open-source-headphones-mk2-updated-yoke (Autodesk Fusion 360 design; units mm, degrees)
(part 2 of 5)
sketch "Shell Hexagon Pattern" plane through (0, 0, 98) normal (0, 0, 1) x axis (-1, 0, 0)
  line L1 (19.1469, -26.6365) -> (22.8469, -28.7727)
  line L2 (19.1469, -22.3642) -> (19.1469, -26.6365)
  line L3 (22.8469, -20.228) -> (19.1469, -22.3642)
  line L4 (26.5469, -22.3642) -> (22.8469, -20.228)
  line L5 (26.5469, -26.6365) -> (26.5469, -22.3642)
  line L6 (22.8469, -28.7727) -> (26.5469, -26.6365)
  line L7 (-26.5469, 22.3642) -> (-22.8469, 20.228)
  line L8 (-26.5469, 26.6365) -> (-26.5469, 22.3642)
  line L9 (-22.8469, 28.7727) -> (-26.5469, 26.6365)
  line L10 (-19.1469, 26.6365) -> (-22.8469, 28.7727)
  line L11 (-19.1469, 22.3642) -> (-19.1469, 26.6365)
  line L12 (-22.8469, 20.228) -> (-19.1469, 22.3642)
  line L13 (19.1469, 22.3642) -> (22.8469, 20.228)
  line L14 (19.1469, 26.6365) -> (19.1469, 22.3642)
  line L15 (22.8469, 28.7727) -> (19.1469, 26.6365)
  line L16 (26.5469, 26.6365) -> (22.8469, 28.7727)
  line L17 (26.5469, 22.3642) -> (26.5469, 26.6365)
  line L18 (22.8469, 20.228) -> (26.5469, 22.3642)
  line L19 (-26.5469, -26.6365) -> (-22.8469, -28.7727)
  line L20 (-26.5469, -22.3642) -> (-26.5469, -26.6365)
  line L21 (-22.8469, -20.228) -> (-26.5469, -22.3642)
  line L22 (-19.1469, -22.3642) -> (-22.8469, -20.228)
  line L23 (-19.1469, -26.6365) -> (-19.1469, -22.3642)
  line L24 (-22.8469, -28.7727) -> (-19.1469, -26.6365)
  curve K1 (-7.3164, 50.178) -> (-7.3164, 50.178)
  line L25 (0, 51) -> (0, 0)
  line L26 (1, 24.5003) -> (0, 24.5003)
  line L27 (4.6, 24.5003) -> (1, 24.5003)
  line L28 (4.6, 20.3434) -> (1, 22.4219)
  line L29 (8.2, 22.4219) -> (4.6, 20.3434)
  line L30 (8.2, 26.5788) -> (8.2, 22.4219)
  line L31 (4.6, 28.6573) -> (8.2, 26.5788)
  line L32 (1, 26.5788) -> (4.6, 28.6573)
  line L33 (1, 22.4219) -> (1, 26.5788)
  line L34 (10.2, 24.5003) -> (8.2, 24.5003)
  line L35 (10.2, 26.5788) -> (13.8, 28.6573)
  line L36 (10.2, 22.4219) -> (10.2, 26.5788)
  line L37 (13.8, 20.3434) -> (10.2, 22.4219)
  line L38 (17.4, 22.4219) -> (13.8, 20.3434)
  line L39 (17.4, 26.5788) -> (17.4, 22.4219)
  line L40 (13.8, 28.6573) -> (17.4, 26.5788)
  line L41 (-1, 26.5788) -> (-1, 22.4219)
  line L42 (-4.6, 28.6573) -> (-1, 26.5788)
  line L43 (-8.2, 26.5788) -> (-4.6, 28.6573)
  line L44 (-8.2, 22.4219) -> (-8.2, 26.5788)
  line L45 (-4.6, 20.3434) -> (-8.2, 22.4219)
  line L46 (-1, 22.4219) -> (-4.6, 20.3434)
  line L47 (-13.8, 28.6573) -> (-10.2, 26.5788)
  line L48 (-17.4, 26.5788) -> (-13.8, 28.6573)
  line L49 (-17.4, 22.4219) -> (-17.4, 26.5788)
  line L50 (-13.8, 20.3434) -> (-17.4, 22.4219)
  line L51 (-10.2, 26.5788) -> (-10.2, 22.4219)
  line L52 (-10.2, 22.4219) -> (-13.8, 20.3434)
  line L53 (-1, 24.5003) -> (0, 24.5003)
  line L54 (16.6, 29.3501) -> (15.6, 27.618)
  line L55 (18.4, 28.3109) -> (14.8, 30.3893)
  line L56 (22, 30.3893) -> (18.4, 28.3109)
  line L57 (22, 34.5462) -> (22, 30.3893)
  line L58 (18.4, 36.6247) -> (22, 34.5462)
  line L59 (14.8, 34.5462) -> (18.4, 36.6247)
  line L60 (14.8, 30.3893) -> (14.8, 34.5462)
  line L61 (5.6, 30.3893) -> (5.6, 34.5462)
  line L62 (9.2, 28.3109) -> (5.6, 30.3893)
  line L63 (12.8, 30.3893) -> (9.2, 28.3109)
  line L64 (12.8, 34.5462) -> (12.8, 30.3893)
  line L65 (5.6, 34.5462) -> (9.2, 36.6247)
  line L66 (9.2, 36.6247) -> (12.8, 34.5462)
  line L67 (-3.6, 30.3893) -> (-3.6, 34.5462)
  line L68 (0, 28.3109) -> (-3.6, 30.3893)
  line L69 (3.6, 30.3893) -> (0, 28.3109)
  line L70 (3.6, 34.5462) -> (3.6, 30.3893)
  line L71 (-3.6, 34.5462) -> (0, 36.6247)
  line L72 (0, 36.6247) -> (3.6, 34.5462)
  line L73 (-12.8, 30.3893) -> (-12.8, 34.5462)
  line L74 (-9.2, 28.3109) -> (-12.8, 30.3893)
  line L75 (-5.6, 30.3893) -> (-9.2, 28.3109)
  line L76 (-5.6, 34.5462) -> (-5.6, 30.3893)
  line L77 (-12.8, 34.5462) -> (-9.2, 36.6247)
  line L78 (-9.2, 36.6247) -> (-5.6, 34.5462)
  line L79 (-14.8, 32.4678) -> (-12.8, 32.4678)
  line L80 (-27.6, 28.3109) -> (-31.2, 30.3893)
  line L81 (-24, 30.3893) -> (-27.6, 28.3109)
  line L82 (-24, 34.5462) -> (-24, 30.3893)
  line L83 (-27.6, 36.6247) -> (-24, 34.5462)
  line L84 (-31.2, 30.3893) -> (-31.2, 34.5462)
  line L85 (-31.2, 34.5462) -> (-27.6, 36.6247)
  line L86 (-18.4, 28.3109) -> (-22, 30.3893)
  line L87 (-14.8, 30.3893) -> (-18.4, 28.3109)
  line L88 (-14.8, 34.5462) -> (-14.8, 30.3893)
  line L89 (-18.4, 36.6247) -> (-14.8, 34.5462)
  line L90 (-22, 30.3893) -> (-22, 34.5462)
  line L91 (-22, 34.5462) -> (-18.4, 36.6247)
  line L92 (24, 32.4678) -> (22, 32.4678)
  line L93 (24, 34.5462) -> (27.6, 36.6247)
  line L94 (24, 30.3893) -> (24, 34.5462)
  line L95 (27.6, 28.3109) -> (24, 30.3893)
  line L96 (31.2, 30.3893) -> (27.6, 28.3109)
  line L97 (31.2, 34.5462) -> (31.2, 30.3893)
  line L98 (27.6, 36.6247) -> (31.2, 34.5462)
  line L99 (30.4, 27.618) -> (29.4, 29.3501)
  line L100 (32.2, 28.6573) -> (35.8, 26.5788)
  line L101 (28.6, 26.5788) -> (32.2, 28.6573)
  line L102 (28.6, 22.4219) -> (28.6, 26.5788)
  line L103 (32.2, 20.3434) -> (28.6, 22.4219)
  line L104 (35.8, 22.4219) -> (32.2, 20.3434)
  line L105 (35.8, 26.5788) -> (35.8, 22.4219)
  line L106 (15.6, 37.3175) -> (16.6, 35.5855)
  line L107 (23, 36.2783) -> (19.4, 38.3568)
  line L108 (26.6, 38.3568) -> (23, 36.2783)
  line L109 (26.6, 42.5137) -> (26.6, 38.3568)
  line L110 (23, 44.5921) -> (26.6, 42.5137)
  line L111 (19.4, 42.5137) -> (23, 44.5921)
  line L112 (19.4, 38.3568) -> (19.4, 42.5137)
  line L113 (10.2, 38.3568) -> (10.2, 42.5137)
  line L114 (13.8, 36.2783) -> (10.2, 38.3568)
  line L115 (17.4, 38.3568) -> (13.8, 36.2783)
  line L116 (17.4, 42.5137) -> (17.4, 38.3568)
  line L117 (10.2, 42.5137) -> (13.8, 44.5921)
  line L118 (13.8, 44.5921) -> (17.4, 42.5137)
  line L119 (1, 38.3568) -> (1, 42.5137)
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  point P1 (0, 0)
  point P28 (0, 0)
  point P29 (0, 51)
  point P30 (0, 24.5003)
  point P32 (4.6, 24.5003)
  point P39 (4.6, 24.5003)
  point P40 (8.2, 24.5003)
  point P62 (15.6, 27.618)
  point P88 (-12.8, 32.4678)
  point P102 (22, 32.4678)
  point P110 (29.4, 29.3501)
  point P118 (16.6, 35.5855)
  point P188 (15.6, 21.3827)
  point P232 (-29.4, 29.3501)
  point P557 (0, 0)
  point P593 (0, 0)
  point P425 (-4.6, -24.5003)
  point P534 (-4.6, -24.5003)
  point P31 (1, 24.5003)
  point P41 (10.2, 24.5003)
  point P54 (-1, 24.5003)
  point P61 (0, 24.5003)
  point P63 (16.6, 29.3501)
  point P89 (-14.8, 32.4678)
  point P103 (24, 32.4678)
  point P111 (30.4, 27.618)
  point P119 (15.6, 37.3175)
  point P156 (6.4, 43.5529)
  point P157 (7.4, 45.285)
  point P189 (16.6, 19.6506)
  point P233 (-30.4, 27.618)
  point P252 (29.4, 13.4152)
  point P253 (30.4, 11.6832)
  point P308 (-35.8, 8.5655)
  point P309 (-37.8, 8.5655)
  point P316 (30.4, 5.4478)
  point P317 (29.4, 3.7157)
  point P441 (-1, -24.5003)
  point P716 (0, -24.5003)
  point P423 (-10.2, -24.5003)
  point P424 (-8.2, -24.5003)
  point P571 (0, -24.5003)
  point P701 (1, -24.5003)
  point P535 (-15.6, -27.618)
  point P537 (-16.6, -29.3501)
  point P717 (12.8, -32.4678)
  point P729 (14.8, -32.4678)
  point P547 (-22, -32.4678)
  point P548 (-24, -32.4678)
  point P549 (-29.4, -29.3501)
  point P550 (-30.4, -27.618)
  point P541 (-16.6, -35.5855)
  point P558 (-15.6, -37.3175)
  point P536 (-7.4, -45.285)
  point P559 (-6.4, -43.5529)
  point P712 (-16.6, -19.6506)
  point P714 (-15.6, -21.3827)
  point P484 (30.4, -27.618)
  point P488 (29.4, -29.3501)
  point P560 (-29.4, -13.4152)
  point P561 (-30.4, -11.6832)
  point P563 (35.8, -8.5655)
  point P564 (37.8, -8.5655)
  point P562 (-30.4, -5.4478)
  point P565 (-29.4, -3.7157)
  coincident P1 P28
  coincident K1 P29
  vertical L25
  coincident L25 P30
  perpendicular L25 L26
  parallel L26 L27
  coincident P32 P39
  midpoint L30 P40
  perpendicular L30 L34
  midpoint L40 P62
  perpendicular L40 L54
  midpoint L73 P88
  perpendicular L73 L79
  midpoint L57 P102
  perpendicular L57 L92
  midpoint L96 P110
  perpendicular L96 L99
  midpoint L59 P118
  perpendicular L59 L106
  midpoint L38 P188
  midpoint L80 P232
  coincident P557 P593
  coincident P425 P534
  dimension "d175" distance P30 P31 = 1
  dimension "d180" distance P31 P32 = 3.6
  dimension "d181" distance P39 L33 = 3.6
  dimension "d182" distance P40 P41 = 2
  dimension "d183" distance P54 P61 = 1
  dimension "d184" distance P62 P63 = 2
  dimension "d185" distance P88 P89 = 2
  dimension "d186" distance P102 P103 = 2
  dimension "d187" distance P110 P111 = 2
  dimension "d188" distance P118 P119 = 2
  dimension "d189" distance P156 P157 = 2
  dimension "d190" distance P188 P189 = 2
  dimension "d191" distance P232 P233 = 2
  dimension "d192" distance P252 P253 = 2
  dimension "d193" distance P308 P309 = 2
  dimension "d194" distance P316 P317 = 2
  dimension "d195" distance P441 P716 = 1
  dimension "d196" distance P425 P441 = 3.6
  dimension "d197" distance = 3.6
  dimension "d198" distance P423 P424 = 2
  dimension "d199" distance P571 P701 = 1
  dimension "d200" distance P535 P537 = 2
  dimension "d201" distance P717 P729 = 2
  dimension "d202" distance P547 P548 = 2
  dimension "d203" distance P549 P550 = 2
  dimension "d204" distance P541 P558 = 2
  dimension "d205" distance P536 P559 = 2
  dimension "d206" distance P712 P714 = 2
  dimension "d207" distance P484 P488 = 2
  dimension "d208" distance P560 P561 = 2
  dimension "d209" distance P563 P564 = 2
  dimension "d210" distance P562 P565 = 2
sketch "Sketch12" plane through (0, 0, 98) normal (0, 0, 1) x axis (-1, 0, 0)
  line L1 (19.1469, -26.6365) -> (22.8469, -28.7727)
  line L2 (19.1469, -22.3642) -> (19.1469, -26.6365)
  line L3 (22.8469, -20.228) -> (19.1469, -22.3642)
  line L4 (26.5469, -22.3642) -> (22.8469, -20.228)
  line L5 (26.5469, -26.6365) -> (26.5469, -22.3642)
  line L6 (22.8469, -28.7727) -> (26.5469, -26.6365)
  line L7 (-26.5469, 22.3642) -> (-22.8469, 20.228)
  line L8 (-26.5469, 26.6365) -> (-26.5469, 22.3642)
  line L9 (-22.8469, 28.7727) -> (-26.5469, 26.6365)
  line L10 (-19.1469, 26.6365) -> (-22.8469, 28.7727)
  line L11 (-19.1469, 22.3642) -> (-19.1469, 26.6365)
  line L12 (-22.8469, 20.228) -> (-19.1469, 22.3642)
  line L13 (19.1469, 22.3642) -> (22.8469, 20.228)
  line L14 (19.1469, 26.6365) -> (19.1469, 22.3642)
  line L15 (22.8469, 28.7727) -> (19.1469, 26.6365)
  line L16 (26.5469, 26.6365) -> (22.8469, 28.7727)
  line L17 (26.5469, 22.3642) -> (26.5469, 26.6365)
  line L18 (22.8469, 20.228) -> (26.5469, 22.3642)
  line L19 (-26.5469, -26.6365) -> (-22.8469, -28.7727)
  line L20 (-26.5469, -22.3642) -> (-26.5469, -26.6365)
  line L21 (-22.8469, -20.228) -> (-26.5469, -22.3642)
  line L22 (-19.1469, -22.3642) -> (-22.8469, -20.228)
  line L23 (-19.1469, -26.6365) -> (-19.1469, -22.3642)
  line L24 (-22.8469, -28.7727) -> (-19.1469, -26.6365)
  curve K1 (-7.3164, 50.178) -> (-7.3164, 50.178)
  curve K2 (0, -48.6) -> (0, 48.6)
  curve K3 (38.6, 0) -> (-38.6, 0)
  closed curve K4 centre (0, 0)
  point P29 (0, 48.6)
  point P30 (0, -48.6)
  point P31 (-38.6, 0)
  point P32 (38.6, 0)
  coincident K4 P29
  coincident K4 P30
  coincident K4 P31
  coincident K4 P32
  dimension "d217" distance K4 = 97.2
  dimension "d218" = 77.2
extrude "Extrude25" cut sketch "Sketch12" profile of L1 L2 L3 L4 L5 L6 L7 L8 L9 L10 L11 L12 L13 L14 L15 L16 L17 L18 L19 L20 L21 L22 L23 L24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 against normal blind 4 bodies "Closed Shell (1) (1)", "Closed Shell (1) (2)", "Closed Shell (1) (3)", "Open Shell"
extrude "Extrude26" add sketch "Shell Hexagon Pattern" against normal blind 4 bodies "Closed Shell (1)", "Closed Shell (1) (1)", "Closed Shell (1) (2)", "Closed Shell (1) (3)"
chamfer "Chamfer8" distance 0.24 distance 1
sketch "Headband Arc" plane through (0, 0, 0) normal (0, 0, 1) x axis (1, 0, 0)
  line L1 (0, -165) -> (0, -75)
  line L2 (85, -165) -> (0, -165)
  line L3 (0, -71.5) -> (0, -75)
  line L4 (88.5, -165) -> (85, -165)
  line L5 (91.4952, -168.75) -> (85, -165)
  line L6 (92.5, -165) -> (85, -165)
  line L7 (81.4952, -186.0705) -> (91.4952, -168.75)
  line L8 (69.8038, -179.3205) -> (81.4952, -186.0705)
  line L9 (73.3038, -173.2583) -> (69.8038, -179.3205)
  line L10 (77.7713, -183.9205) -> (87.7713, -166.6)
  line L11 (81.2713, -177.8583) -> (73.3038, -173.2583)
  line L12 (87.2289, -149.2103) -> (91.4952, -168.75)
  closed curve K1 centre (0, -165)
  closed curve K2 centre (0, -165)
  point P4 (85, -165)
  point P7 (88.5, -165)
  point P16 (81.2713, -177.8583)
  point P17 (87.2289, -149.2103)
  point P18 (84.7553, -171.8238)
  point P19 (88.4796, -167.0089)
  point P2 (0, -75)
  point P3 (0, -165)
  point P6 (0, -71.5)
  point P9 (91.4952, -168.75)
  point P11 (81.4952, -186.0705)
  point P12 (69.8038, -179.3205)
  point P13 (73.3038, -173.2583)
  vertical L1
  perpendicular L1 L2
  coincident P4 K1
  parallel L1 L3
  parallel L2 L4
  coincident P7 K2
  horizontal L6
  perpendicular L5 L7
  perpendicular L7 L8
  perpendicular L8 L9
  coincident L10 P16
  perpendicular L10 L11
  coincident P17 K2
  coincident L10 P18
  coincident L5 P19
  dimension "d225" distance P2 P3 = 90
  dimension "d226" distance P3 P4 = 85
  dimension "d227" distance P2 P6 = 3.5
  dimension "d228" distance P4 P7 = 3.5
  dimension "d229" angle L5 L6 = 30
  dimension "d230" distance P4 P9 = 7.5
  dimension "d231" distance P9 P11 = 20
  dimension "d232" distance P11 P12 = 13.5
  dimension "d233" distance P12 P13 = 7
  dimension "d234" = 4.3
  dimension "d235" distance P9 P17 = 20
extrude "Extrude1" new body sketch "Headband Arc" profile of K1 L3 L4 K2 L5 L7 L8 L9 L10 L11 L12 along normal blind 36
sketch "Yoke Hole" plane through (-60.1971, -104.2644, 0) normal (-0.5, -0.866, 0) x axis (0.866, -0.5, 0)
  line L1 (163.6122, 0) -> (150.1122, 0)
  line L2 (163.6122, 36) -> (163.6122, 0)
  line L3 (150.1122, 36) -> (163.6122, 36)
  line L4 (150.1122, 0) -> (150.1122, 36)
  line L5 (152.6122, 18) -> (150.1122, 18)
  line L6 (155.7122, 18) -> (152.6122, 18)
  line L7 (152.6122, 14.9) -> (158.8122, 14.9)
  line L8 (152.6122, 21.1) -> (152.6122, 14.9)
  line L9 (158.8122, 21.1) -> (152.6122, 21.1)
  line L10 (158.8122, 14.9) -> (158.8122, 21.1)
  line L11 (152.6122, 21.1) -> (158.8122, 14.9)
  line L12 (158.8122, 21.1) -> (152.6122, 14.9)
  circle C1 centre (155.7122, 18) radius 3.1
  circle C2 centre (155.7122, 18) radius 2.1
  point P6 (150.1122, 18)
  point P13 (155.7122, 18)
  point P8 (155.7122, 18)
  point P14 (155.7122, 18)
  point P7 (152.6122, 18)
  point P15 (155.7122, 18)
  point P11 (152.6122, 21.1)
  point P12 (158.8122, 21.1)
  point P10 (152.6122, 14.9)
  midpoint L4 P6
  perpendicular L4 L5
  parallel L5 L6
  horizontal L7
  perpendicular L7 L8
  parallel L7 L9
  parallel L8 L10
  coincident L11 P13
  coincident L12 P13
  coincident P8 P13
  coincident P13 P14
  coincident P7 C1
  coincident P13 P15
  dimension "d240" distance P6 P7 = 2.5
  dimension "d241" distance P7 P8 = 3.1
  dimension "d242" distance P11 P12 = 6.2
  dimension "d243" distance P10 P11 = 6.2
  dimension "d244" diameter C2 = 4.2
extrude "Extrude2" cut sketch "Yoke Hole" profile of C2 against normal blind 7
extrude "Extrude3" cut sketch "Yoke Hole" profile of L7 L8 L9 C1 C2 against normal blind 5
sketch "Sketch2" plane through (141.6923, -81.8061, 0) normal (0.866, -0.5, 0) x axis (0.5, 0.866, 0)
  line L1 (-100.3942, 0) -> (-120.3942, 0)
  line L2 (-100.3942, 36) -> (-100.3942, 0)
  line L3 (-120.3942, 36) -> (-100.3942, 36)
  line L4 (-120.3942, 0) -> (-120.3942, 36)
  line L5 (-120.3942, 35) -> (-100.3942, 1)
  line L6 (-105.6231, 35.681) -> (-117.6911, 23.613)
  line L7 (-100.3942, 1) -> (-100.3942, 35)
  line L8 (-103.0973, 12.387) -> (-114.3233, 23.613)
  line L9 (-103.9392, 33.9971) -> (-114.3233, 23.613)
  line L10 (-113.2007, 12.387) -> (-120.217, 19.4033)
  line L11 (-100.3942, 35) -> (-120.3942, 35)
  line L12 (-106.4651, 12.387) -> (-117.6911, 23.613)
  line L13 (-120.3942, 36) -> (-100.3942, 36)
  line L14 (-120.217, 5.3707) -> (-113.2007, 12.387)
  line L15 (-100.5714, 30.6293) -> (-107.5877, 23.613)
  line L16 (-115.1653, 0.319) -> (-103.0973, 12.387)
  line L17 (-118.5331, 21.0872) -> (-118.5331, 3.6868)
  line L18 (-118.5331, 3.6868) -> (-107.307, 14.9128)
  line L19 (-100.3942, 0) -> (-120.3942, 0)
  line L20 (-107.307, 33.9971) -> (-103.9392, 33.9971)
  line L21 (-120.3942, 1) -> (-100.3942, 1)
  line L22 (-113.4813, 2.0029) -> (-116.8492, 2.0029)
  line L23 (-116.8492, 2.0029) -> (-106.4651, 12.387)
  line L24 (-102.2553, 32.3132) -> (-102.2553, 14.9128)
  line L25 (-102.2553, 14.9128) -> (-110.9555, 23.613)
  line L26 (-108.7103, 18) -> (-112.0781, 18)
  line L27 (-107.307, 9.8611) -> (-118.5331, 21.0872)
  line L28 (-120.3942, 35) -> (-120.3942, 1)
  line L29 (-100.5714, 16.5967) -> (-107.5877, 23.613)
  line L30 (-100.3942, 35) -> (-120.3942, 1)
  line L31 (-102.2553, 32.3132) -> (-110.9555, 23.613)
  line L32 (-100.3942, 36) -> (-100.3942, 0)
  line L33 (-120.3942, 0) -> (-120.3942, 36)
  point P11 (-113.4813, 2.0029)
  point P23 (-107.307, 33.9971)
  point P38 (-112.0781, 18)
  point P37 (-108.7103, 18)
  point P36 (-110.3942, 18)
  point P33 (-120.3942, 35)
  point P35 (-100.3942, 35)
  point P39 (-120.3942, 1)
  coincident P11 L16
  coincident P23 L6
  parallel L20 L22
  midpoint P38 L12
  midpoint P37 L8
  horizontal L21
  perpendicular L21 L28
  parallel L11 L21
  parallel L7 L28
  coincident P36 L5
  coincident P36 L30
  midpoint P36 L26
  dimension "d249" distance P33 P35 = 20
  dimension "d250" distance P33 P39 = 34
sketch "Left" plane through (52.1639, 11.3894, 0) normal (0.977, 0.2133, 0) x axis (-0.2133, 0.977, 0)
  dimension "d253" = 15
sketch "Sketch4" plane through (0, 0, 36) normal (0, 0, 1) x axis (-1, 0, 0)
  line L1 (-91.4952, 168.75) -> (-81.4952, 186.0705)
  line L2 (-87.2289, 149.2103) -> (-91.4952, 168.75)
  line L3 (0, 75) -> (0, 71.5)
  line L4 (-81.2713, 177.8583) -> (-84.7553, 171.8238)
  line L5 (-73.3038, 173.2583) -> (-81.2713, 177.8583)
  line L6 (-69.8038, 179.3205) -> (-73.3038, 173.2583)
  line L7 (-81.4952, 186.0705) -> (-69.8038, 179.3205)
  line L8 (-86.3713, 169.0249) -> (-81.2713, 177.8583)
  line L9 (-84.7531, 158.1446) -> (-86.3713, 169.0249)
  closed curve K1 centre (0, 165)
  closed curve K2 centre (0, 165)
  point P9 (-81.2713, 177.8583)
  point P12 (-81.2713, 177.8583)
  point P14 (-84.7531, 158.1446)
  point P13 (-86.3713, 169.0249)
  coincident P9 P12
  perpendicular L5 L8
  coincident K2 P14
  dimension "d258" distance P12 P13 = 10.2
  dimension "d259" distance P13 P14 = 11
chamfer "Chamfer1" distance 1 distance 1
extrude "Extrude6" cut sketch "Sketch4" profile of K2 L8 L9 against normal blind 36
sketch "Sketch12" plane through (-56.6971, -98.2023, 0) normal (0.5, 0.866, 0) x axis (-0.866, 0.5, 0)
  line L1 (-150.1122, 1) -> (-151.1122, 0)
  line L2 (-150.1122, 35) -> (-150.1122, 1)
  line L3 (-151.1122, 36) -> (-150.1122, 35)
  line L4 (-159.3122, 36) -> (-151.1122, 36)
  line L5 (-159.3122, 0) -> (-159.3122, 36)
  line L6 (-151.1122, 0) -> (-159.3122, 0)
  line L7 (-151.5552, 18) -> (-153.6337, 14.4)
  line L8 (-153.6337, 21.6) -> (-151.5552, 18)
  line L9 (-157.7906, 21.6) -> (-153.6337, 21.6)
  line L10 (-159.8691, 18) -> (-157.7906, 21.6)
  line L11 (-157.7906, 14.4) -> (-159.8691, 18)
  line L12 (-153.6337, 14.4) -> (-157.7906, 14.4)
  circle C1 centre (-155.7122, 18) radius 2.1
  point P8 (-155.7122, 18)
  point P15 (-155.7122, 18)
  coincident P8 P15
  dimension "d341" distance P15 L12 = 3.6
extrude "Extrude19" cut sketch "Sketch12" profile of L5 L10 L11 along normal blind 6
extrude "Extrude20" add sketch "Sketch12" profile of L5 L10 L11 along normal blind 2
mirror "Mirror1" mirrorStitchTolerance 0.1
sketch "Sketch5" plane through (-141.6923, -81.8061, 0) normal (-0.866, -0.5, 0) x axis (0.5, -0.866, 0)
  line L1 (120.3942, 1) -> (100.3942, 1)
  line L2 (120.3942, 35) -> (120.3942, 1)
  line L3 (100.3942, 35) -> (120.3942, 35)
  line L4 (100.3942, 1) -> (100.3942, 35)
  line L5 (108.7103, 18) -> (112.0781, 18)
  line L6 (120.3942, 35) -> (100.3942, 35)
  line L7 (100.3942, 1) -> (120.3942, 1)
  line L8 (120.3942, 0) -> (100.3942, 0)
  line L9 (103.9392, 2.0029) -> (114.3233, 12.387)
  line L10 (100.3942, 36) -> (120.3942, 36)
  line L11 (100.3942, 0) -> (100.3942, 36)
  line L12 (118.5331, 14.9128) -> (118.5331, 32.3132)
  line L13 (102.2553, 3.6868) -> (110.9555, 12.387)
  line L14 (120.3942, 36) -> (120.3942, 0)
  line L15 (120.217, 30.6293) -> (113.2007, 23.613)
  line L16 (100.3942, 0) -> (100.3942, 36)
  line L17 (100.5714, 19.4033) -> (107.5877, 12.387)
  line L18 (103.0973, 23.613) -> (114.3233, 12.387)
  line L19 (100.3942, 36) -> (120.3942, 36)
  line L20 (118.5331, 32.3132) -> (107.307, 21.0872)
  line L21 (106.4651, 23.613) -> (117.6911, 12.387)
  line L22 (102.2553, 3.6868) -> (102.2553, 21.0872)
  line L23 (120.3942, 1) -> (120.3942, 35)
  line L24 (100.3942, 1) -> (120.3942, 35)
  line L25 (107.307, 26.1389) -> (118.5331, 14.9128)
  line L26 (120.3942, 0) -> (100.3942, 0)
  line L27 (105.6231, 0.319) -> (117.6911, 12.387)
  line L28 (100.3942, 35) -> (100.3942, 1)
  line L29 (113.4813, 33.9971) -> (116.8492, 33.9971)
  line L30 (113.2007, 23.613) -> (120.217, 16.5967)
  line L31 (120.3942, 36) -> (120.3942, 0)
  line L32 (100.5714, 5.3707) -> (107.5877, 12.387)
  line L33 (115.1653, 35.681) -> (103.0973, 23.613)
  line L34 (102.2553, 21.0872) -> (110.9555, 12.387)
  line L35 (116.8492, 33.9971) -> (106.4651, 23.613)
  line L36 (120.3942, 1) -> (100.3942, 35)
  line L37 (107.307, 2.0029) -> (103.9392, 2.0029)
  point P26 (113.4813, 33.9971)
  point P27 (107.307, 2.0029)
  point P28 (112.0781, 18)
  point P36 (108.7103, 18)
  point P35 (110.3942, 18)
  point P29 (120.3942, 1)
  point P31 (100.3942, 1)
  point P43 (120.3942, 35)
  coincident P26 L33
  coincident P27 L27
  parallel L29 L37
  midpoint P28 L21
  midpoint P36 L18
  perpendicular L6 L23
  parallel L6 L7
  parallel L23 L28
  coincident P35 L36
  coincident P35 L24
  midpoint P35 L5
  dimension "d264" distance P29 P31 = 20
  dimension "d265" distance P29 P43 = 34
sketch "Right" plane through (-52.1639, 11.3894, 0) normal (-0.977, 0.2133, 0) x axis (-0.2133, -0.977, 0)
  line L1 (184.3831, 1) -> (164.3831, 1)
  line L2 (184.3831, 35) -> (184.3831, 1)
  line L3 (164.3831, 35) -> (184.3831, 35)
  line L4 (164.3831, 1) -> (164.3831, 35)
  line L5 (184.3831, 36) -> (184.3831, 0)
  line L6 (164.3831, 36) -> (184.3831, 36)
  curve K1
  curve K2
  curve K3
  curve K4
  line L7 (164.3831, 0) -> (164.3831, 36)
  line L8 (184.3831, 0) -> (164.3831, 0)
  dimension "d266" Text1-Height = 15
extrude "Extrude7" cut sketch "Left" against normal blind 0.5
extrude "Extrude8" cut sketch "Sketch2" profile of L6 L8 L9 L10 L12 L14 L15 L16 L17 L18 L20 L22 L23 L24 L25 L27 L29 L31 against normal blind 0.5
extrude "Extrude9" cut sketch "Right" against normal blind 0.5
extrude "Extrude10" cut sketch "Sketch5" profile of L9 L12 L13 L15 L17 L18 L20 L21 L22 L25 L27 L29 L30 L32 L33 L34 L35 L37 against normal blind 0.5
sketch "Yoke" plane through (0, 0, 0) normal (0, 0, 1) x axis (1, 0, 0)
  line L1 (50, -150) -> (45, -150)
  line L2 (0, -90) -> (0, -95)
  line L3 (50, -150) -> (45, -150)
  line L4 (50, -155) -> (50, -150)
  line L5 (45, -155) -> (50, -155)
  line L6 (45, -150) -> (45, -155)
  line L7 (39, -155) -> (50, -155)
  line L8 (39, -161) -> (39, -155)
  line L9 (50, -161) -> (39, -161)
  line L10 (50, -155) -> (50, -161)
  line L11 (18, -90) -> (0, -90)
  line L12 (18, -97) -> (18, -90)
  line L13 (0, -97) -> (18, -97)
  line L14 (0, -90) -> (0, -97)
  line L15 (30, -102) -> (18, -90)
  line L16 (34.9706, -90) -> (18, -90)
  line L17 (50, -155) -> (45, -155)
  line L18 (50, -158) -> (50, -155)
  line L19 (45, -158) -> (50, -158)
  line L20 (45, -155) -> (45, -158)
  closed curve K1 centre (0, -150)
  closed curve K2 centre (0, -150)
  point P17 (30, -102)
  point P20 (50, -158)
  point P4 (45, -150)
  point P8 (50, -150)
  point P10 (45, -155)
  point P9 (50, -155)
  point P11 (39, -155)
  point P13 (50, -161)
  point P6 (0, -90)
  point P14 (18, -90)
  point P16 (0, -97)
  concentric K1 K2
  horizontal L3
  vertical L4
  horizontal L5
  vertical L6
  horizontal L7
  vertical L8
  horizontal L9
  vertical L10
  horizontal L11
  vertical L12
  horizontal L13
  vertical L14
  horizontal L16
  coincident K1 P17
  horizontal L17
  vertical L18
  horizontal L19
  vertical L20
  midpoint L10 P20
  dimension "d275" distance K2 = 110
  dimension "d276" = 90
  dimension "d277" distance K1 = 120
  dimension "d278" = 100
  dimension "d279" distance P4 P8 = 5
  dimension "d280" distance P4 P10 = 5
  dimension "d281" distance P9 P11 = 11
  dimension "d282" distance P9 P13 = 6
  dimension "d283" distance P6 P14 = 18
  dimension "d284" distance P6 P16 = 7
  dimension "d285" angle L15 L16 = 45
extrude "Extrude11" new body sketch "Yoke" profile of L7 L8 L9 L10 L19 L20 along normal blind 6 bodies "Yoke +-20 Degree Rotation"
extrude "Extrude12" add sketch "Yoke" profile of K2 K1 L1 L2 L3 L4 L5 L6 L7 L10 L11 L12 L13 L14 L15 L17 L18 L19 L20 along normal blind 10
chamfer "Chamfer3" distance 61 distance 4
fillet "Fillet2" radius 3
chamfer "Chamfer9" distance 1.5
sketch "Sketch9" plane through (0, -97, 0) normal (0, -1, 0) x axis (1, 0, 0)
  line L1 (12.0248, 0) -> (0, 0)
  line L2 (12.0248, 10) -> (12.0248, 0)
  line L3 (0, 10) -> (12.0248, 10)
  line L4 (0, 0) -> (0, 10)
  line L5 (5.5, 0) -> (0, 0)
  line L6 (5.5, 10) -> (5.5, 0)
  line L7 (0, 10) -> (5.5, 10)
  line L8 (0, 0) -> (0, 10)
  point P1 (0, 0)
  point P6 (0, 0)
  point P7 (5.5, 0)
  horizontal L5
  vertical L6
  horizontal L7
  vertical L8
  coincident P1 P6
  dimension "d302" distance P6 P7 = 5.5
extrude "Extrude15" cut sketch "Sketch9" profile of L1 L3 L4 L5 L6 L7 L8 against normal blind 2
mirror "Mirror2" mirrorStitchTolerance 0.1
sketch "Yoke socket" plane through (0, -95, 0) normal (0, -1, 0) x axis (1, 0, 0)
  line L1 (5.5, 0) -> (-5.5, 0)
  line L2 (5.5, 10) -> (5.5, 0)
  line L3 (-5.5, 10) -> (5.5, 10)
  line L4 (-5.5, 0) -> (-5.5, 10)
  line L5 (2.913, 6.0603) -> (-2.913, 3.9397)
  line L6 (4.6231, 1.3618) -> (2.913, 6.0603)
  line L7 (-1.2029, -0.7587) -> (4.6231, 1.3618)
  line L8 (-2.913, 3.9397) -> (-1.2029, -0.7587)
  line L9 (-4.6231, 1.3618) -> (1.2029, -0.7587)
  line L10 (-2.913, 6.0603) -> (-4.6231, 1.3618)
  line L11 (2.913, 3.9397) -> (-2.913, 6.0603)
  line L12 (1.2029, -0.7587) -> (2.913, 3.9397)
  line L13 (0, 1.5861) -> (0, 0.6861)
  line L14 (-1.613, 0.999) -> (0, 1.5861)
  line L15 (-1.7165, 1.5861) -> (0, 1.5861)
  line L16 (1.613, 0.999) -> (0, 1.5861)
  line L17 (1.7165, 1.5861) -> (0, 1.5861)
  circle C1 centre (0, 5) radius 3.1
  circle C2 centre (0, 5) radius 4.3139
  circle C3 centre (0, 5) radius 5
  point P6 (0, 5)
  point P10 (0, 5)
  point P11 (-2.913, 3.9397)
  point P19 (0, 0.6861)
  point P21 (-1.613, 0.999)
  point P23 (1.613, 0.999)
  point P12 (2.913, 6.0603)
  point P14 (-1.2029, -0.7587)
  point P16 (-2.913, 6.0603)
  point P17 (2.913, 3.9397)
  point P18 (-4.6231, 1.3618)
  point P20 (0, 1.5861)
  coincident P6 P10
  coincident C1 P11
  coincident C2 P19
  vertical L13
  horizontal L15
  coincident C2 P21
  horizontal L17
  coincident C2 P23
  dimension "d307" diameter C1 = 6.2
  dimension "d308" diameter C3 = 10
  dimension "d316" distance P11 P12 = 6.2
  dimension "d317" distance P11 P14 = 5
  dimension "d318" distance P16 P17 = 6.2
  dimension "d319" distance P16 P18 = 5
  dimension "d327" distance P19 P20 = 0.9
  dimension "d328" angle L14 L15 = 20
  dimension "d329" angle L16 L17 = 20
extrude "Extrude16" cut sketch "Yoke socket" profile of C1 C2 L6 L10 L14 L16 against normal blind 5
sketch "Screw Holder" plane through (0, 0, 0) normal (0, 0, 1) x axis (1, 0, 0)
  line L1 (3, -110) -> (-3, -110)
  line L2 (3, -113) -> (3, -110)
  line L3 (-3, -113) -> (3, -113)
  line L4 (-3, -110) -> (-3, -113)
  circle C1 centre (0, -110) radius 5
  circle C2 centre (0, -110) radius 2.1
  circle C3 centre (0, -110) radius 3
  point P5 (-3, -110)
  point P6 (3, -110)
  point P8 (-3, -113)
  concentric C1 C2
  concentric C1 C3
  horizontal L1
  vertical L2
  horizontal L3
  vertical L4
  coincident C3 P5
  dimension "d330" diameter C1 = 10
  dimension "d331" diameter C2 = 4.2
  dimension "d332" diameter C3 = 6
  dimension "d333" distance P5 P6 = 6
  dimension "d334" distance P5 P8 = 3
extrude "Extrude17" new body sketch "Screw Holder" profile of C1 C3 L2 L3 L4 along normal blind 2 bodies "Screw Holder"
extrude "Extrude18" add sketch "Screw Holder" profile of C2 C3 L2 L3 L4 along normal blind 12.2
sketch "Sketch13" plane through (0, 0, 0) normal (0, 0, 1) x axis (1, 0, 0)
  line L1 (-18, -134.6) -> (18, -134.6)
  line L2 (-18, -125.4) -> (-18, -134.6)
  line L3 (18, -125.4) -> (-18, -125.4)
  line L4 (18, -134.6) -> (18, -125.4)
  line L5 (-18, -125.4) -> (18, -134.6)
  line L6 (18, -125.4) -> (-18, -134.6)
  line L7 (-13, -134.6) -> (13, -134.6)
  line L8 (-13, -125.4) -> (-13, -134.6)
  line L9 (13, -125.4) -> (-13, -125.4)
  line L10 (13, -134.6) -> (13, -125.4)
  line L11 (-13, -125.4) -> (13, -134.6)
  line L12 (13, -125.4) -> (-13, -134.6)
  line L13 (-13, -133.6) -> (13, -133.6)
  line L14 (-13, -131.6) -> (13, -131.6)
  line L15 (0, -126.9) -> (0, -125.4)
  line L16 (0, -124.8431) -> (3.6, -126.9215)
  line L17 (-3.6, -126.9215) -> (0, -124.8431)
  line L18 (-3.6, -131.0785) -> (-3.6, -126.9215)
  line L19 (0, -133.1569) -> (-3.6, -131.0785)
  line L20 (3.6, -131.0785) -> (0, -133.1569)
  line L21 (3.6, -126.9215) -> (3.6, -131.0785)
  line L22 (3.6, -131.0785) -> (-3.6, -131.0785)
  line L23 (3.6, -134.6) -> (3.6, -131.0785)
  line L24 (-3.6, -134.6) -> (3.6, -134.6)
  line L25 (-3.6, -131.0785) -> (-3.6, -134.6)
  circle C1 centre (0, -129) radius 2.1
  point P6 (0, -130)
  point P11 (0, -130)
  point P16 (0, -125.4)
  point P17 (0, -126.9)
  point P18 (0, -129)
  point P25 (0, -129)
  point P4 (-18, -125.4)
  point P5 (18, -125.4)
  point P3 (-18, -134.6)
  point P9 (-13, -125.4)
  point P10 (13, -125.4)
  point P22 (-3.6, -131.0785)
  point P26 (3.6, -131.0785)
  horizontal L1
  perpendicular L1 L2
  parallel L1 L3
  parallel L2 L4
  coincident L5 P6
  coincident L6 P6
  horizontal L7
  perpendicular L7 L8
  parallel L7 L9
  parallel L8 L10
  coincident L11 P11
  coincident L12 P11
  coincident P6 P11
  midpoint L3 P16
  perpendicular L3 L15
  coincident P17 C1
  coincident P18 P25
  horizontal L22
  vertical L23
  horizontal L24
  vertical L25
  dimension "d346" distance P4 P5 = 36
  dimension "d347" distance P3 P4 = 9.2
  dimension "d348" distance P9 P10 = 26
  dimension "d349" = 1
  dimension "d350" = 3
  dimension "d351" distance P16 P17 = 1.5
  dimension "d352" diameter C1 = 4.2
  dimension "d353" distance P25 L21 = 3.6
  dimension "d354" distance P22 P26 = 7.2
extrude "Extrude21" new body sketch "Sketch13" profile of L1 L2 L3 L4 L7 L8 L9 L10 L13 L14 C1 L16 L17 L18 L21 L23 L24 L25 along normal blind 10 bodies "Headband Clip"
extrude "Extrude22" cut sketch "Sketch13" profile of L1 L3 L7 L9 L13 L14 C1 L16 L17 L18 L21 L23 L24 L25 along normal blind 6
extrude "Extrude23" cut sketch "Sketch13" profile of C1 along normal blind 8
extrude "Extrude24" add sketch "Sketch13" profile of L1 L3 L7 L9 L13 L14 C1 L16 L17 L18 L21 L23 L24 L25 along normal blind 2
sketch "Sketch15" plane through (0, -134.6, 0) normal (0, -1, 0) x axis (1, 0, 0)
  line L1 (18, 0) -> (-18, 0)
  line L2 (18, 10) -> (18, 0)
  line L3 (-18, 10) -> (18, 10)
  line L4 (-18, 0) -> (-18, 10)
  line L5 (-3.6, 6) -> (-3.6, 2)
  line L6 (3.6, 6) -> (-3.6, 6)
  line L7 (3.6, 2) -> (3.6, 6)
  line L8 (-3.6, 2) -> (3.6, 2)
  line L9 (-2, 8) -> (2, 8)
  line L10 (-2, 12) -> (-2, 8)
  line L11 (2, 12) -> (-2, 12)
  line L12 (2, 8) -> (2, 12)
  line L13 (-2, 12) -> (2, 8)
  line L14 (2, 12) -> (-2, 8)
  line L15 (-4, 10) -> (-2, 12)
  line L16 (4, 10) -> (2, 12)
  line L17 (0, 7) -> (0, 6)
  line L18 (0, 8.25) -> (0, 7)
  line L19 (-1.5, 7) -> (1.5, 7)
  line L20 (-1.5, 9.5) -> (-1.5, 7)
  line L21 (1.5, 9.5) -> (-1.5, 9.5)
  line L22 (1.5, 7) -> (1.5, 9.5)
  line L23 (-1.5, 9.5) -> (1.5, 7)
  line L24 (1.5, 9.5) -> (-1.5, 7)
  point P15 (0, 10)
  point P16 (-4, 10)
  point P17 (4, 10)
  point P18 (0, 6)
  point P25 (0, 8.25)
  point P20 (0, 8.25)
  point P13 (-2, 12)
  point P14 (2, 12)
  point P12 (-2, 8)
  point P19 (0, 7)
  point P23 (-1.5, 9.5)
  point P24 (1.5, 9.5)
  point P22 (-1.5, 7)
  horizontal L9
  perpendicular L9 L10
  parallel L9 L11
  parallel L10 L12
  coincident L13 P15
  coincident L14 P15
  midpoint L3 P15
  coincident L3 P16
  perpendicular L13 L15
  coincident L3 P17
  perpendicular L15 L16
  midpoint L6 P18
  perpendicular L6 L17
  parallel L17 L18
  horizontal L19
  perpendicular L19 L20
  parallel L19 L21
  parallel L20 L22
  coincident L23 P25
  coincident L24 P25
  coincident P20 P25
  dimension "d383" distance P13 P14 = 4
  dimension "d384" distance P12 P13 = 4
  dimension "d387" distance P18 P19 = 1
  dimension "d388" distance P19 P20 = 1.25
  dimension "d389" distance P23 P24 = 3
  dimension "d390" distance P22 P23 = 2.5
extrude "Extrude28" add sketch "Sketch15" profile of L3 L10 L11 L12 L15 L16 against normal blind 9.2
extrude "Extrude29" cut sketch "Sketch15" profile of L19 L20 L21 L22 against normal blind 3
sketch "Sketch16" plane through (0, 0, 12) normal (0, 0, 1) x axis (-1, 0, 0)
  line L1 (-2, 134.6) -> (2, 134.6)
  line L2 (-2, 125.4) -> (-2, 134.6)
  line L3 (2, 125.4) -> (-2, 125.4)
  line L4 (2, 134.6) -> (2, 125.4)
  line L5 (0, 130.6) -> (0, 134.6)
  line L6 (-1.5, 132.6) -> (1.5, 132.6)
  line L7 (-1.5, 128.6) -> (-1.5, 132.6)
  line L8 (1.5, 128.6) -> (-1.5, 128.6)
  line L9 (1.5, 132.6) -> (1.5, 128.6)
  line L10 (-1.5, 128.6) -> (1.5, 132.6)
  line L11 (1.5, 128.6) -> (-1.5, 132.6)
  point P6 (0, 134.6)
  point P12 (0, 130.6)
  point P7 (0, 130.6)
  point P10 (-1.5, 128.6)
  point P11 (1.5, 128.6)
  midpoint L1 P6
  perpendicular L1 L5
  horizontal L6
  perpendicular L6 L7
  parallel L6 L8
  parallel L7 L9
  coincident L10 P12
  coincident L11 P12
  coincident P7 P12
  dimension "d393" distance P6 P7 = 4
  dimension "d394" distance P10 P11 = 3
extrude "Extrude30" cut sketch "Sketch16" profile of L6 L7 L8 L9 against normal blind 2.5
sketch "Sketch17" plane through (1.5, 0, 0) normal (-1, 0, 0) x axis (0, -1, 0)
  line L1 (134.6, 9.5) -> (134.6, 7)
  line L2 (132.6, 9.5) -> (134.6, 9.5)
  line L3 (132.6, 12) -> (132.6, 9.5)
  line L4 (128.6, 12) -> (132.6, 12)
  line L5 (128.6, 9.5) -> (128.6, 12)
  line L6 (131.6, 9.5) -> (128.6, 9.5)
  line L7 (131.6, 7) -> (131.6, 9.5)
  line L8 (134.6, 7) -> (131.6, 7)
  line L9 (134.6, 7) -> (131.6, 9.5)
  line L10 (131.6, 9.5) -> (128.6, 12)
  line L11 (132.6, 11.5) -> (132.6, 12)
  line L12 (134.6, 9.5) -> (132.6, 11.5)
  point P8 (131.6, 9.5)
  point P10 (131.6, 9.5)
  point P2 (134.6, 7)
  point P11 (134.6, 7)
  point P6 (128.6, 12)
  point P12 (128.6, 12)
  point P5 (132.6, 12)
  point P13 (132.6, 12)
  point P3 (134.6, 9.5)
  point P15 (134.6, 9.5)
  point P14 (132.6, 11.5)
  coincident P8 P10
  coincident P2 P11
  coincident P6 P12
  coincident P5 P13
  perpendicular L4 L11
  coincident P3 P15
  dimension "d397" distance P13 P14 = 0.5
extrude "Extrude31" cut sketch "Sketch17" profile of L2 L3 L12 along normal blind 3
extrude "Extrude32" add sketch "Sketch17" profile of L5 L6 L7 L8 L9 L10 along normal blind 3
chamfer "Chamfer6" distance 2
chamfer "Chamfer7" distance 3.5
copy_paste_bodies "CopyPasteBodies3"
move "Move3"
work_plane "WorkPlane3" AlongDistance 0
sketch "Custom Shell" plane through (0, 0, 134) normal (0, 0, -1) x axis (-1, 0, 0)
  curve K1 (-35, 0) -> (35, 0)
  curve K2 (0, -45) -> (0, 45)
  curve K3 (0, 48.6) -> (0, -48.6)
  curve K4 (-38.6, 0) -> (38.6, 0)
  curve K5 (0, -45.5) -> (0, 45.5)
  curve K6 (35.5, 0) -> (-35.5, 0)
  closed curve K7 centre (0, 0)
  closed curve K8 centre (0, 0)
  closed curve K9 centre (0, 0)
  point P3 (35, 0)
  point P4 (-35, 0)
  point P5 (0, 45)
  point P6 (0, -45)
  point P1 (0, 0)
  point P2 (0, 0)
  point P8 (0, -48.6)
  point P9 (0, 48.6)
  point P10 (38.6, 0)
  point P11 (-38.6, 0)
  point P7 (0, 0)
  point P13 (0, 45.5)
  point P14 (0, -45.5)
  point P15 (-35.5, 0)
  point P16 (35.5, 0)
  point P12 (0, 0)
  coincident K7 P3
  coincident K7 P4
  coincident K7 P5
  coincident K7 P6
  coincident P1 P2
  horizontal K1
  coincident K8 P8
  coincident K8 P9
  coincident K8 P10
  coincident K8 P11
  coincident P1 P7
  perpendicular K1 K3
  coincident K9 P13
  coincident K9 P14
  coincident K9 P15
  coincident K9 P16
  coincident P1 P12
  perpendicular K4 K5
  dimension "d702" distance K7 = 70
  dimension "d703" = 90
  dimension "d704" distance K8 = 97.2
  dimension "d705" = 77.2
  dimension "d715" distance K9 = 91
  dimension "d716" = 71
extrude "Extrude44" cut sketch "Custom Shell" profile of K7 K8 against normal blind 4 bodies "Custom Shell Open Grill"
extrude "Extrude45" add sketch "Custom Shell" profile of K7 K8 against normal blind 4
chamfer "Chamfer12" distance 3
offset_faces "OffsetFaces3" distance -0.2
extrude "Extrude46" add sketch "Custom Shell" profile of K8 K9 against normal blind 3
chamfer "Chamfer14" distance 3
delete_face "DeleteFace1"
copy_paste_bodies "CopyPasteBodies4"
move "Move4"
sketch "Closed Shell" plane through (0, 0, 178) normal (0, 0, 1) x axis (-1, 0, 0)
  curve K1 (0, 48.4) -> (0, 48.4)
  line L1 (19.1469, -26.6365) -> (22.8469, -28.7727)
  line L2 (19.1469, -22.3642) -> (19.1469, -26.6365)
  line L3 (22.8469, -20.228) -> (19.1469, -22.3642)
  line L4 (26.5469, -22.3642) -> (22.8469, -20.228)
  line L5 (26.5469, -26.6365) -> (26.5469, -22.3642)
  line L6 (22.8469, -28.7727) -> (26.5469, -26.6365)
  line L7 (-19.1469, 22.3642) -> (-19.1469, 26.6365)
  line L8 (-22.8469, 20.228) -> (-19.1469, 22.3642)
  line L9 (-26.5469, 22.3642) -> (-22.8469, 20.228)
  line L10 (-26.5469, 26.6365) -> (-26.5469, 22.3642)
  line L11 (-22.8469, 28.7727) -> (-26.5469, 26.6365)
  line L12 (-19.1469, 26.6365) -> (-22.8469, 28.7727)
  line L13 (26.5469, 22.3642) -> (26.5469, 26.6365)
  line L14 (22.8469, 20.228) -> (26.5469, 22.3642)
  line L15 (19.1469, 22.3642) -> (22.8469, 20.228)
  line L16 (19.1469, 26.6365) -> (19.1469, 22.3642)
  line L17 (22.8469, 28.7727) -> (19.1469, 26.6365)
  line L18 (26.5469, 26.6365) -> (22.8469, 28.7727)
  line L19 (-19.1469, -22.3642) -> (-22.8469, -20.228)
  line L20 (-19.1469, -26.6365) -> (-19.1469, -22.3642)
  line L21 (-22.8469, -28.7727) -> (-19.1469, -26.6365)
  line L22 (-26.5469, -26.6365) -> (-22.8469, -28.7727)
  line L23 (-26.5469, -22.3642) -> (-26.5469, -26.6365)
  line L24 (-22.8469, -20.228) -> (-26.5469, -22.3642)
  curve K2 (0, 45) -> (0, -45)
  curve K3 (-35, 0) -> (35, 0)
  closed curve K4 centre (0, 0)
  point P29 (0, -45)
  point P30 (0, 45)
  point P31 (35, 0)
  point P32 (-35, 0)
  point P1 (0, 0)
  point P28 (0, 0)
  coincident K4 P29
  coincident K4 P30
  coincident K4 P31
  coincident K4 P32
  coincident P1 P28
  vertical K2
  dimension "d718" distance K4 = 90
  dimension "d719" = 70
extrude "Extrude47" add sketch "Closed Shell" profile of L1 L2 L3 L4 L5 L6 L7 L8 L9 L10 L11 L12 L13 L14 L15 L16 L17 L18 L19 L20 L21 L22 L23 L24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 against normal blind 4
fillet "Fillet1" radius 1
sketch "Sketch20" plane through (0, 0, 22) normal (0, 0, 1) x axis (-1, 0, 0)
  line L1 (-8, 54.1239) -> (-8, 51.8694)
  line L2 (8, 51.8694) -> (8, 54.1239)
  line L3 (17.2573, 46.032) -> (18.1032, 47.8443)
  line L4 (6, 53.0308) -> (6, 50.2477)
  line L5 (-6, 53.0308) -> (6, 53.0308)
  line L6 (-6, 50.2477) -> (-6, 53.0308)
  line L7 (-18.1032, 47.8443) -> (-17.2573, 46.032)
  line L8 (-27.3973, -19.1838) -> (-24.0432, -16.8352)
  line L9 (-24.0432, 16.8352) -> (-27.3973, 19.1838)
  line L10 (-17.8191, 17.8191) -> (-19.4454, 19.4454)
  line L11 (-8, 32.5308) -> (-8, 23.8964)
  line L12 (8, 23.8964) -> (8, 32.5308)
  line L13 (19.4454, 19.4454) -> (17.8191, 17.8191)
  line L14 (27.3973, 19.1838) -> (24.0432, 16.8352)
  line L15 (24.0432, -16.8352) -> (27.3973, -19.1838)
  line L16 (-15.6326, -25.0174) -> (-17.7523, -28.4096)
  line L17 (17.7523, -28.4096) -> (15.6326, -25.0174)
  line L18 (45, 5.5) -> (-45, 5.5)
  line L19 (45, -5.5) -> (45, 5.5)
  line L20 (-45, -5.5) -> (45, -5.5)
  line L21 (-45, 5.5) -> (-45, -5.5)
  line L22 (45, -5.5) -> (-45, 5.5)
  line L23 (-45, -5.5) -> (45, 5.5)
  line L24 (-37, 5.5) -> (-37, -5.5)
  line L25 (37, -5.5) -> (37, 5.5)
  closed curve K1 centre (0, 0)
  closed curve K2 centre (0, 0)
  closed curve K3 centre (0, 0)
  closed curve K4 centre (0, 0)
  closed curve K5 centre (0, 0)
  arc A1 centre (0, 0) radius 27.5 clockwise from (26.4189, -7.6348) to (-26.4189, -7.6348)
  closed curve K6 centre (0, 0)
  closed curve K7 centre (0, 0)
  closed curve K8 centre (0, 0)
  arc A2 centre (0, 0) radius 27.5 clockwise from (-26.4189, 7.6348) to (-19.4454, 19.4454)
  arc A3 centre (0, 0) radius 25.2 clockwise from (-17.8191, 17.8191) to (-8, 23.8964)
  arc A4 centre (0, 0) radius 33.5 clockwise from (-8, 32.5308) to (8, 32.5308)
  arc A5 centre (0, 0) radius 25.2 clockwise from (8, 23.8964) to (17.8191, 17.8191)
  arc A6 centre (0, 0) radius 27.5 clockwise from (19.4454, 19.4454) to (26.4189, 7.6348)
  closed curve K9 centre (0, 0)
  closed curve K10 centre (0, 0)
  closed curve K11 centre (0, 0)
  arc A7 centre (0, 0) radius 29.5 clockwise from (15.6326, -25.0174) to (-15.6326, -25.0174)
  arc A8 centre (0, 0) radius 33.5 clockwise from (17.7523, -28.4096) to (-17.7523, -28.4096)
  circle C1 centre (22.8469, 24.5003) radius 2.2
  circle C2 centre (22.8469, -24.5003) radius 2.2
  circle C3 centre (-22.8469, 24.5003) radius 2.2
  circle C4 centre (-22.8469, -24.5003) radius 2.2
  point P47 (0, 0)
  point P1 (0, 0)
  point P45 (45, -5.5)
  point P46 (-45, -5.5)
  point P44 (45, 5.5)
  horizontal L18
  perpendicular L18 L19
  parallel L18 L20
  parallel L19 L21
  coincident L22 P47
  coincident L23 P47
  coincident P1 P47
  dimension "d591" distance P45 P46 = 90
  dimension "d592" distance P44 P45 = 11
  dimension "d593" = 8
  dimension "d594" = 8
extrude "Extrude37" add sketch "Sketch20" profile of K1 L18 L19 L20 L21 L24 L25 along normal blind 9
extrude "Extrude38" add sketch "Sketch20" profile of K1 L18 L19 L20 L21 against normal blind 2
sketch "Sketch21" plane through (45, 0, 0) normal (1, 0, 0) x axis (0, 1, 0)
  line L1 (5.5, 31) -> (5.5, 20)
  line L2 (-5.5, 31) -> (5.5, 31)
  line L3 (-5.5, 20) -> (-5.5, 31)
  line L4 (5.5, 20) -> (-5.5, 20)
  line L5 (3.0075, 21) -> (3.0075, 20)
  line L6 (5.5, 31) -> (5.5, 20)
  line L7 (2.2627, 23.2373) -> (6.1518, 27.1263)
  line L8 (1.0945, 28.507) -> (-1.0945, 22.493)
  line L9 (-0.0255, 30) -> (-0.0255, 31)
  line L10 (-5.5, 31) -> (5.5, 31)
  line L11 (3.0075, 20) -> (4.0738, 20)
  line L12 (-5.5, 20) -> (-5.5, 22)
  line L13 (4.0738, 20) -> (4.0738, 21)
  line L14 (-5.5, 29) -> (-3.5, 29)
  line L15 (-3.5, 29) -> (-3.5, 31)
  line L16 (0.9745, 30) -> (-0.0255, 30)
  line L17 (-3.5, 20) -> (-5.5, 20)
  line L18 (-0.0255, 31) -> (0.9745, 31)
  line L19 (-5.5, 20) -> (-5.5, 31)
  line L20 (5.5, 20) -> (-5.5, 20)
  line L21 (6.1518, 27.1263) -> (1.6263, 31.6518)
  line L22 (0.9745, 31) -> (0.9745, 30)
  line L23 (1.6263, 31.6518) -> (-2.2627, 27.7627)
  line L24 (-2.2627, 27.7627) -> (2.2627, 23.2373)
  line L25 (-1.0945, 22.493) -> (4.0738, 20.6119)
  line L26 (-3.5, 31) -> (-5.5, 31)
  line L27 (-3.5, 22) -> (-3.5, 20)
  line L28 (6.2628, 26.6259) -> (1.0945, 28.507)
  line L29 (4.0738, 20.6119) -> (6.2628, 26.6259)
  line L30 (-5.5, 22) -> (-3.5, 22)
  line L31 (-5.5, 31) -> (-5.5, 29)
  line L32 (4.0738, 21) -> (3.0075, 21)
  circle C1 centre (-3.5, 29) radius 2
  circle C2 centre (-3.5, 22) radius 2
  circle C3 centre (0, 25.5) radius 3.2
  point P12 (1.0945, 28.507)
  point P28 (-0.0255, 30)
  point P20 (0.9745, 31)
  point P36 (3.0075, 21)
  point P30 (4.0738, 20)
  point P11 (-5.5, 31)
  point P29 (-5.5, 31)
  point P6 (-5.5, 20)
  point P10 (-5.5, 20)
  point P8 (-3.5, 22)
  point P26 (-3.5, 22)
  point P7 (-3.5, 20)
  point P25 (-3.5, 29)
  point P32 (-3.5, 29)
  point P27 (-3.5, 31)
  point P15 (-1.0945, 22.493)
  point P16 (2.2627, 23.2373)
  point P19 (-2.2627, 27.7627)
  point P31 (0.9745, 30)
  point P35 (4.0738, 21)
  point P33 (-5.5, 29)
  point P9 (-5.5, 22)
  coincident P12 C3
  horizontal L18
  vertical L9
  horizontal L16
  vertical L22
  coincident P28 L23
  coincident P20 L23
  coincident P20 L10
  horizontal L11
  vertical L5
  horizontal L32
  vertical L13
  coincident P36 L25
  coincident P30 L20
  horizontal L26
  vertical L15
  horizontal L14
  vertical L31
  coincident P11 P29
  horizontal L17
  vertical L27
  horizontal L30
  vertical L12
  coincident P6 P10
  coincident P8 P26
  coincident P7 C2
  coincident P25 P32
  coincident P27 C1
  dimension "d599" diameter C3 = 6.4
  dimension "d600" distance P12 P15 = 6.4
  dimension "d601" distance P16 P19 = 6.4
  dimension "d602" distance P20 P31 = 1
  dimension "d603" distance P30 P35 = 1
  dimension "d604" distance P27 P29 = 2
  dimension "d605" distance P29 P33 = 2
  dimension "d606" distance P6 P7 = 2
  dimension "d607" distance P6 P9 = 2
sketch "Sketch22" plane through (-45, 0, 0) normal (-1, 0, 0) x axis (0, -1, 0)
  line L1 (5.5, 31) -> (5.5, 20)
  line L2 (-5.5, 31) -> (5.5, 31)
  line L3 (-5.5, 20) -> (-5.5, 31)
  line L4 (5.5, 20) -> (-5.5, 20)
  line L5 (-1.0945, 28.507) -> (1.0945, 22.493)
  line L6 (-5.5, 31) -> (-5.5, 20)
  line L7 (3.5, 31) -> (5.5, 31)
  line L8 (5.5, 31) -> (-5.5, 31)
  line L9 (5.5, 20) -> (5.5, 31)
  line L10 (-2.2627, 23.2373) -> (-6.1518, 27.1263)
  line L11 (5.5, 20) -> (5.5, 22)
  line L12 (-6.1518, 27.1263) -> (-1.6263, 31.6518)
  line L13 (5.5, 31) -> (5.5, 29)
  line L14 (-3.0075, 21) -> (-3.0075, 20)
  line L15 (5.5, 22) -> (3.5, 22)
  line L16 (3.5, 22) -> (3.5, 20)
  line L17 (-0.9745, 31) -> (-0.9745, 30)
  line L18 (-4.0738, 20.6119) -> (-6.2628, 26.6259)
  line L19 (-1.6263, 31.6518) -> (2.2627, 27.7627)
  line L20 (0.0255, 30) -> (0.0255, 31)
  line L21 (-3.0075, 20) -> (-4.0738, 20)
  line L22 (-0.9745, 30) -> (0.0255, 30)
  line L23 (-6.2628, 26.6259) -> (-1.0945, 28.507)
  line L24 (5.5, 29) -> (3.5, 29)
  line L25 (-5.5, 31) -> (-5.5, 20)
  line L26 (-4.0738, 21) -> (-3.0075, 21)
  line L27 (5.5, 31) -> (-5.5, 31)
  line L28 (-5.5, 20) -> (5.5, 20)
  line L29 (1.0945, 22.493) -> (-4.0738, 20.6119)
  line L30 (3.5, 20) -> (5.5, 20)
  line L31 (2.2627, 27.7627) -> (-2.2627, 23.2373)
  line L32 (5.5, 20) -> (5.5, 31)
  line L33 (0.0255, 31) -> (-0.9745, 31)
  line L34 (-4.0738, 20) -> (-4.0738, 21)
  line L35 (-5.5, 20) -> (5.5, 20)
  line L36 (3.5, 29) -> (3.5, 31)
  circle C1 centre (3.5, 29) radius 2
  circle C2 centre (0, 25.5) radius 3.2
  circle C3 centre (3.5, 22) radius 2
  point P20 (-1.0945, 28.507)
  point P35 (0.0255, 30)
  point P17 (-0.9745, 31)
  point P29 (-3.0075, 21)
  point P37 (-4.0738, 20)
  point P15 (5.5, 31)
  point P36 (5.5, 31)
  point P6 (5.5, 20)
  point P10 (5.5, 20)
  point P9 (3.5, 22)
  point P33 (3.5, 22)
  point P7 (3.5, 20)
  point P30 (3.5, 29)
  point P39 (3.5, 29)
  point P34 (3.5, 31)
  point P18 (1.0945, 22.493)
  point P19 (-2.2627, 23.2373)
  point P23 (2.2627, 27.7627)
  point P40 (-0.9745, 30)
  point P26 (-4.0738, 21)
  point P28 (5.5, 29)
  point P8 (5.5, 22)
  coincident P20 C2
  coincident P35 L19
  coincident P17 L19
  coincident P17 L27
  coincident P29 L29
  coincident P37 L28
  coincident P15 P36
  coincident P6 P10
  coincident P9 P33
  coincident P7 C3
  coincident P30 P39
  coincident P34 C1
  dimension "d608" diameter C2 = 6.4
  dimension "d609" distance P18 P20 = 6.4
  dimension "d610" distance P19 P23 = 6.4
  dimension "d611" distance P17 P40 = 1
  dimension "d612" distance P26 P37 = 1
  dimension "d613" distance P34 P36 = 2
  dimension "d614" distance P28 P36 = 2
  dimension "d615" distance P6 P7 = 2
  dimension "d616" distance P6 P8 = 2
extrude "Extrude39" cut sketch "Sketch22" profile of C1 C2 C3 against normal blind 6
extrude "Extrude40" cut sketch "Sketch21" profile of C1 C2 C3 against normal blind 6
extrude "Extrude41" add sketch "Sketch21" profile of L2 L3 L4 L5 C1 L9 L10 C2 C3 L19 L20 L23 L25 along normal blind 3
extrude "Extrude42" add sketch "Sketch22" profile of L1 L2 L4 L8 L9 L14 L19 C1 C2 L20 C3 L27 L28 L29 L32 L35 along normal blind 3
fillet "Fillet5" radius 0.8
offset_faces "OffsetFaces2" distance 0.5
chamfer "Chamfer11" distance 1.5 Rotate Angle 50
copy_paste_bodies "CopyPasteBodies1"
move "Move1"
copy_paste_bodies "CopyPasteBodies2"
move "Move2"
component_from_bodies "Body->Comp2"
copy_paste_bodies "CutPasteBodies1"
